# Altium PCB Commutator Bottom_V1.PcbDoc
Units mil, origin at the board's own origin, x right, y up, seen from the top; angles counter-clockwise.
Board outline 2389.49 x 2550.21 mil, 2 copper layers (Top Layer, Bottom Layer), stack 61.756 mil thick; 13 components, 19 nets, 72 pads, 18 vias.
Unrouted connection lines stored in the file: 13.
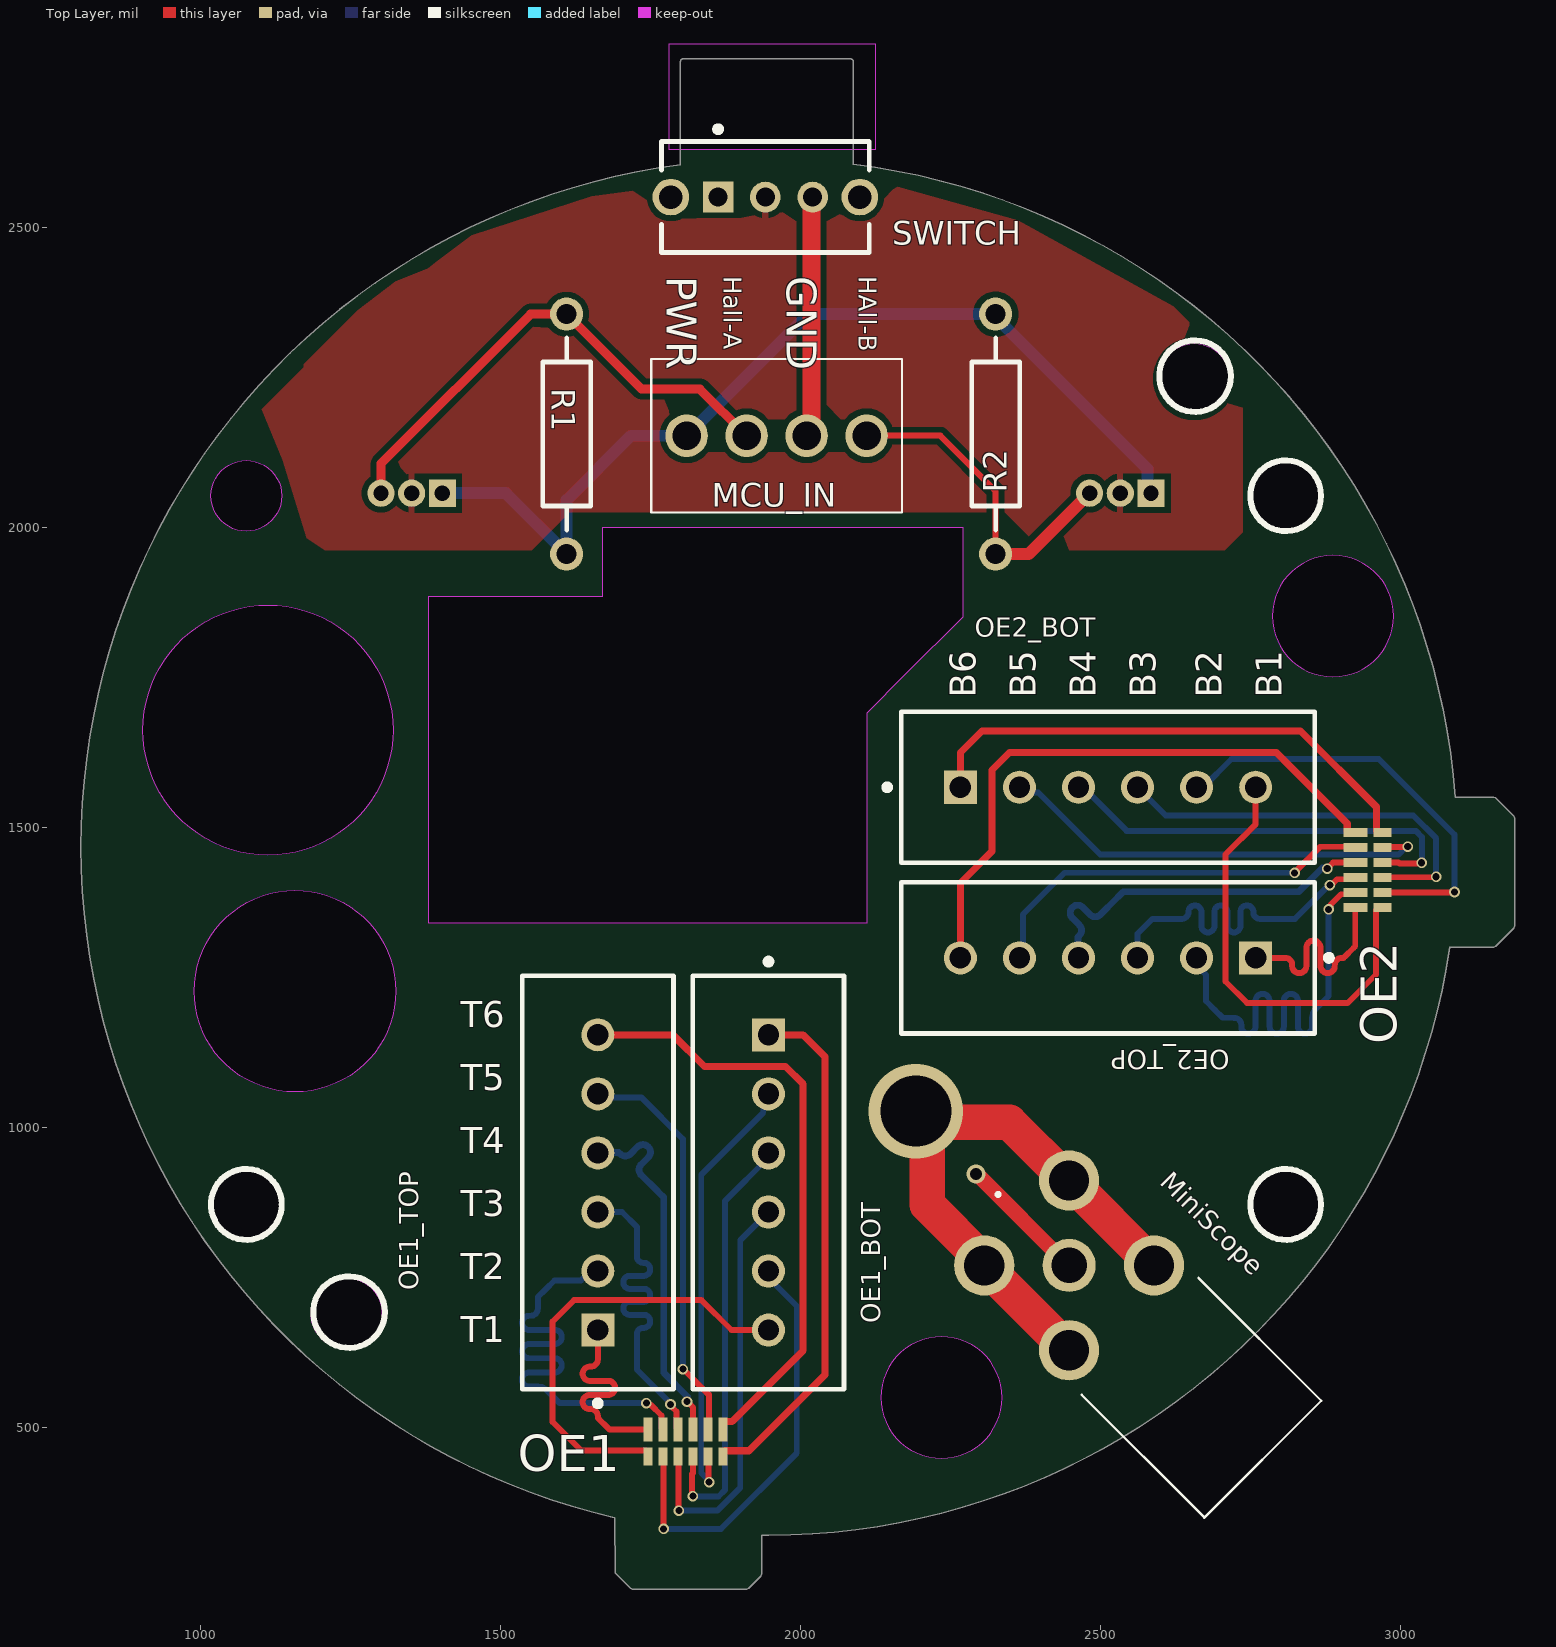
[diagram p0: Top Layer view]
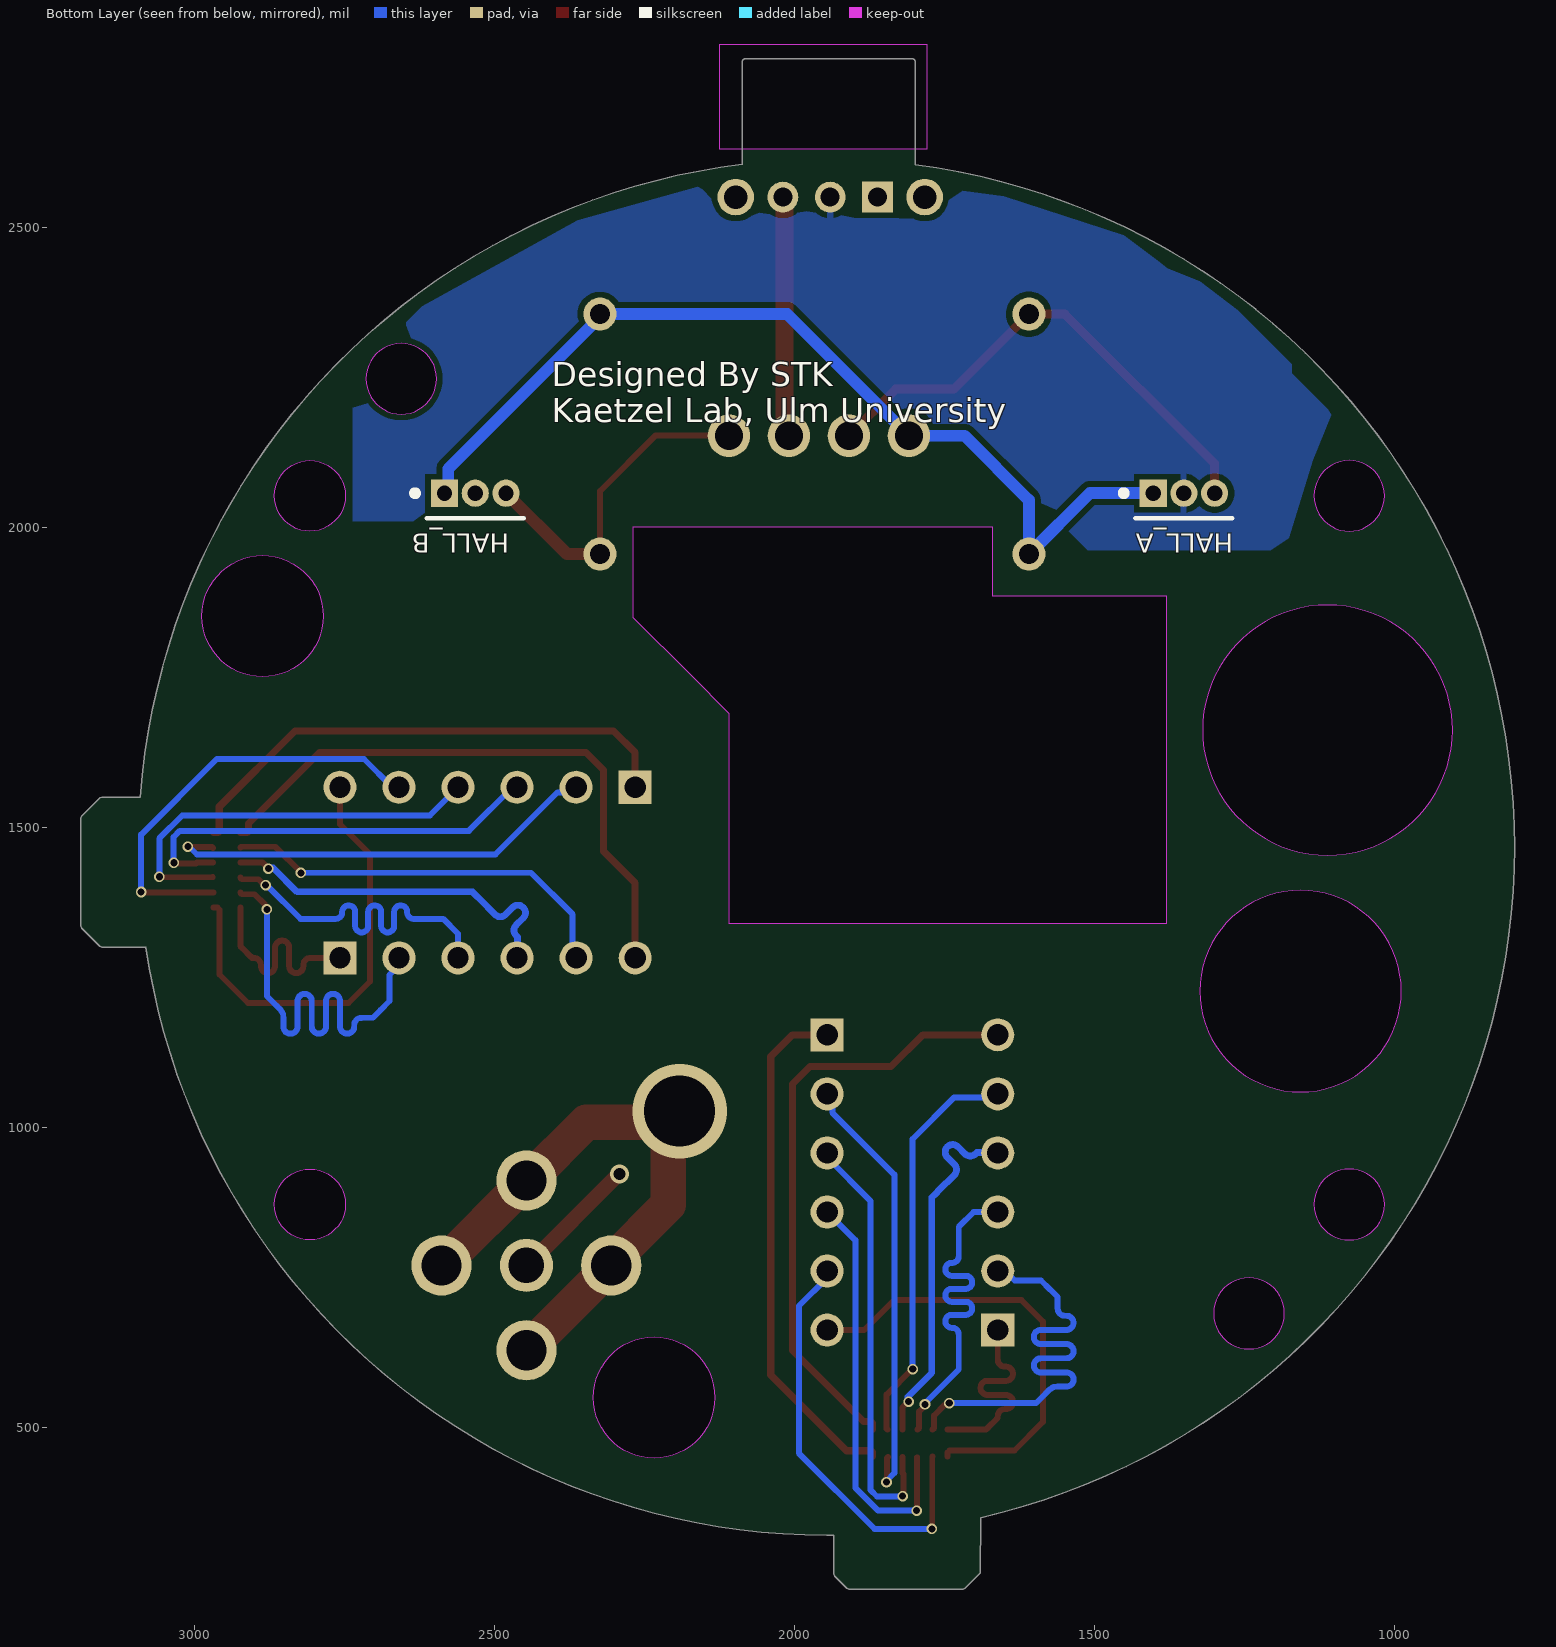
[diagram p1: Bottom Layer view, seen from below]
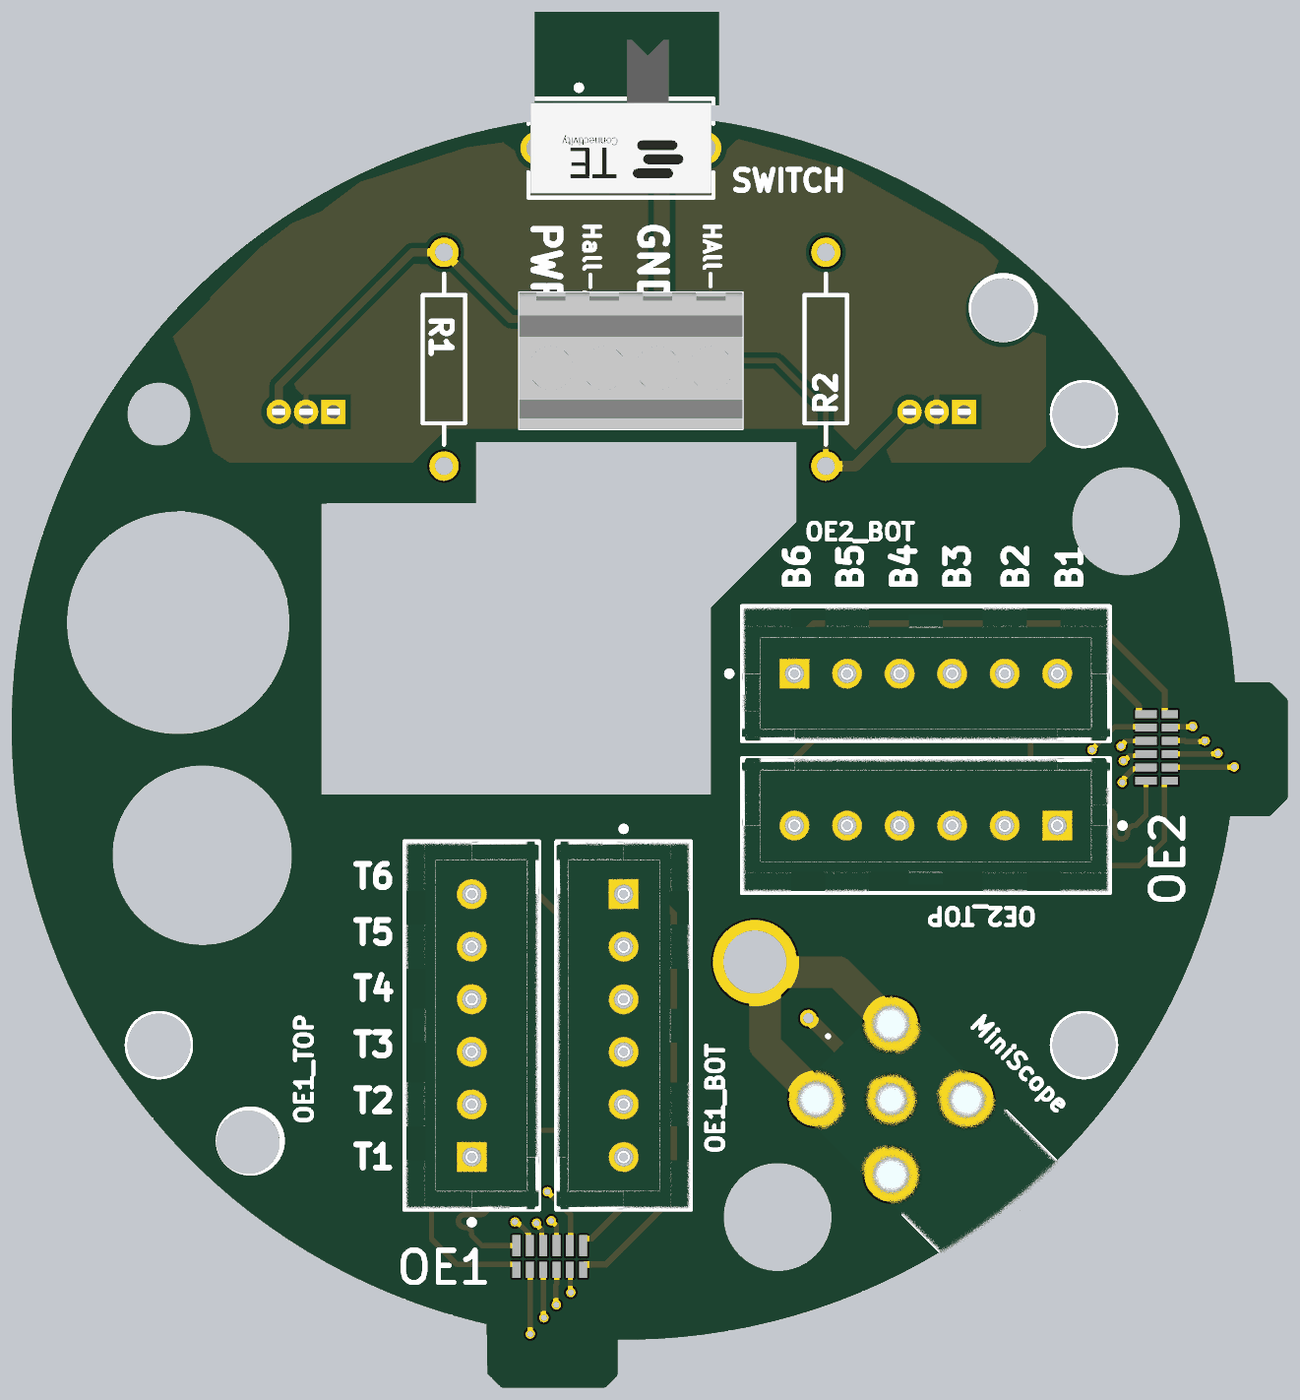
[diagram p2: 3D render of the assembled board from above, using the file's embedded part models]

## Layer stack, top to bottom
Top Solder: solder mask 1, SM-001, Dk 4
Top Layer: signal copper 1.378
Dielectric 1: core 59, Core-043, Dk 4.3
Bottom Layer: signal copper 1.378
Bottom Solder: solder mask 1, SM-001, Dk 4

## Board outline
1691.45,256.45 1716.45,231.45 1720,229.98 1910,229.98 1913.55,231.45 1933.55,251.45 1935.02,255 1935.02,319.88 ccw(c1947.28,1466.56) 1947.28,319.81 ccw(c1947.28,1466.56) 3081.86,1299.98 3155,1299.98 3158.55,1301.45 3188.55,1331.45 3190.02,1335 3190.02,1515 3188.55,1518.55 3158.55,1548.55 3155,1550.01 3090.98,1550.01 ccw(c1947.28,1466.56) 2087.61,2604.69 2087.61,2776.25 ccw(c2083.65,2776.25) 2083.65,2780.2 1803.73,2780.2 ccw(c1803.73,2776.25) 1799.78,2776.25 1799.78,2603.78 ccw(c1947.28,1466.56) 800.53,1466.56 ccw(c1947.28,1466.56) 1689.98,349.05
cut-out: 1112.28,1453.17 cw(c1112.28,1661.56) 903.89,1661.56 cw(c1112.28,1661.56) 1112.28,1869.95 cw(c1112.28,1661.56) 1320.66,1661.56 cw(c1112.28,1661.56)
cut-out: 2786.16,1851.56 ccw(c2887.28,1851.56) 2887.28,1750.44 ccw(c2887.28,1851.56) 2988.39,1851.56 ccw(c2887.28,1851.56) 2887.28,1952.68 ccw(c2887.28,1851.56)
cut-out: 2656.13,2188.06 cw(c2656.13,2247.11) 2597.08,2247.11 cw(c2656.13,2247.11) 2656.13,2306.17 cw(c2656.13,2247.11) 2715.19,2247.11 cw(c2656.13,2247.11)
cut-out: 1243.17,630.31 cw(c1243.17,689.37) 1184.12,689.37 cw(c1243.17,689.37) 1243.17,748.42 cw(c1243.17,689.37) 1302.23,689.37 cw(c1243.17,689.37)
cut-out: 1076.13,1993.06 cw(c1076.13,2052.11) 1017.08,2052.11 cw(c1076.13,2052.11) 1076.13,2111.17 cw(c1076.13,2052.11) 1135.19,2052.11 cw(c1076.13,2052.11)
cut-out: 2749.36,2052.11 ccw(c2808.42,2052.11) 2808.42,1993.06 ccw(c2808.42,2052.11) 2867.47,2052.11 ccw(c2808.42,2052.11) 2808.42,2111.17 ccw(c2808.42,2052.11)
cut-out: 2749.36,871.01 ccw(c2808.42,871.01) 2808.42,811.95 ccw(c2808.42,871.01) 2867.47,871.01 ccw(c2808.42,871.01) 2808.42,930.06 ccw(c2808.42,871.01)
cut-out: 1076.13,811.95 cw(c1076.13,871.01) 1017.08,871.01 cw(c1076.13,871.01) 1076.13,930.06 cw(c1076.13,871.01) 1135.19,871.01 cw(c1076.13,871.01)
cut-out: 2133.61,549.18 ccw(c2234.73,549.18) 2234.73,448.06 ccw(c2234.73,549.18) 2335.85,549.18 ccw(c2234.73,549.18) 2234.73,650.29 ccw(c2234.73,549.18)
cut-out: 1157.28,1058.56 cw(c1157.28,1226.56) 989.27,1226.56 cw(c1157.28,1226.56) 1157.28,1394.56 cw(c1157.28,1226.56) 1325.28,1226.56 cw(c1157.28,1226.56)
cut-out: 1380,1340 1380,1885 1670,1885 1670,2000 2270,2000 2270,1850 2173.75,1753.75 2110,1690 2110,1340
cut-out: 1780,2630 2125,2630 2125,2805 1780,2805

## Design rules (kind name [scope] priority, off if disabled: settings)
Clearance [All] p1: gap=10 ignorepadtopadclearanceinfootprint=FALSE except(0: Arc-Hole Track-Hole SMDPad-Hole THPad-Hole Via-Hole Fill-Hole Poly-Hole Region-Hole Text-Hole)
PolygonConnect [All] p1: connectstyle=Relief reliefconductorwidth=10 reliefentries=4 polygonreliefangle="90 Angle" airgapwidth=10
RoutingVias [All] p1: holewidth=28 width=50 viastyle="Through Hole" minholewidth=28 minwidth=50 maxholewidth=28 maxwidth=50
SolderMaskExpansion [All] p1: expansion=4 istentingtop=FALSE
Width [All] p1: maxlimit=10 minlimit=10 preferedwidth=10
30 further rules are at their usual default settings.

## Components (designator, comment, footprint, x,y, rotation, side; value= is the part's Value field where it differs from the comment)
HALL_A "SS49E" FP-SS49E-MFG 1351.72,2052.11 r180 bottom (schematic designator HAll_A)
HALL_B "SS49E" FP-SS49E-MFG 2532.83,2052.11 r180 bottom
MCU_IN "282834-4" 2828344 1810,2152.19 r0 top
MiniScope "132136RP" 132136RP 2447.49,769.43 r315 top
OE1 "RHD2000-CABLE-DAQ-SIDE" RHD2000_EVAL_BOARD_OMNETICS_PZN-12-AA 1808.1,410.59 r180 top
OE1_BOT "B06B-XASK-1(LF)(SN)" FP-B06B-XASK-1_LF_SN-MFG 1946.33,907.67 r90 top
OE1_TOP "B06B-XASK-1(LF)(SN)" FP-B06B-XASK-1_LF_SN-MFG 1661.96,907.67 r270 top
OE2 "RHD2000-CABLE-DAQ-SIDE" RHD2000_EVAL_BOARD_OMNETICS_PZN-12-AA 3009.41,1428.1 r270 top
OE2_BOT "B06B-XASK-1(LF)(SN)" FP-B06B-XASK-1_LF_SN-MFG 2512.33,1566.33 r180 top
OE2_TOP "B06B-XASK-1(LF)(SN)" FP-B06B-XASK-1_LF_SN-MFG 2512.33,1281.96 r0 top
R1 "" AXIAL-0.4 1610,2155 r270 top value="6 - 10K"
R2 "" AXIAL-0.4 2325,2155 r90 top value="6 - 10K"
SWITCH "1825232-1" FP-1825232-1-MFG 1941.26,2550 r0 top

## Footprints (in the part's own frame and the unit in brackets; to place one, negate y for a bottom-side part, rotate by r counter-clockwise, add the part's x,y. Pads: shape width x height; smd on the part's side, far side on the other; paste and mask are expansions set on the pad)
132136RP [mm]
  round 2.25 hole 1.5: 1(0,0)
  round 2.55 hole 1.7: 2(-2.54,-2.54) 3(2.54,-2.54) 4(2.54,2.54) 5(-2.54,2.54)
  silkscreen extent -4.3,-3.5 11.6,3.5, body extent -3.5,-3.5 11.6,3.5, height 9.96
2828344 [mm]
  round 1.8 hole 1.2: 1(0,0) 2(2.54,0) 3(5.08,0) 4(7.62,0)
  silkscreen extent -1.5,-3.25 9.12,3.25, body extent -1.5,-3.25 9.12,3.25, height 9.93
AXIAL-0.4 [mm] "Axial Device, Thru-Hole; 2 Leads; 0.4 in Pin Spacing"
  round 1.4 hole 0.85: 1(-5.08,0) 2(5.08,0)
  silkscreen extent -4.06,-1.02 4.06,1.02
FP-1825232-1-MFG [mm]
  rect 1.3x1.3 hole 0.8 paste-1000 mask+0: 1(-2,0)
  round 1.3 hole 0.8 paste-1000 mask+0: 2(0,0) 3(2,0)
  round 1.55 hole 1 paste-1000 mask+0: 4(-4,0) 5(4,0)
  silkscreen extent -4.4,-2.35 4.4,3, body extent -4.87,-5.45 4.88,2.45, height 0.25
FP-B06B-XASK-1_LF_SN-MFG [mm]
  rect 1.4x1.4 hole 0.9 paste-1000 mask+0: 1(6.25,0)
  round 1.4 hole 0.9 paste-1000 mask+0: 2(3.75,0) 3(1.25,0) 4(-1.25,0) 5(-3.75,0) 6(-6.25,0)
  silkscreen extent -8.75,-3.2 9.47,3.2, body extent -8.85,-3.3 8.85,3.3, height 0.25
FP-SS49E-MFG [mm]
  rect 1.15x1.15 hole 0.65 paste-1000 mask+0: 1(-1.3,0.11)
  round 1.15 hole 0.65 paste-1000 mask+0: 2(0,0.11) 3(1.3,0.11)
  silkscreen extent -2.68,-0.95 2.05,0.23, body extent -2.05,-0.8 2.05,0.8, height 5.1
RHD2000_EVAL_BOARD_OMNETICS_PZN-12-AA [mil]
  rect 15x30 smd: B1(62.5,-40) B2(37.5,-40) B3(12.5,-40) B4(-12.5,-40) B5(-37.5,-40) B6(-62.5,-40)
  rect 15x40 smd: T1(62.5,-85) T2(37.5,-85) T3(12.5,-85) T4(-12.5,-85) T5(-37.5,-85) T6(-62.5,-85)

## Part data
HALL_A HALL_B: library part CMP-11168-000005-1, "SENSOR LINEAR ANALOG RADIAL", Case/Package=TO-226-3, Input Current=10mA, Leakage Current=10uA, Max Operating Temperature=150°C, Max Supply Voltage=6.5V, Max Supply Voltage (DC)=10V, Min Operating Temperature=-40°C, Min Supply Voltage=2.7V, Min Supply Voltage (DC)=4V, Operating Supply Current=6mA, Output Current=1.5mA, Output Voltage=1.75mV, Package Quantity=1000
MCU_IN: "Connector", Manufacturer_Name="TE Connectivity"
MiniScope: "Connector", Manufacturer_Name=Amphenol
OE1 OE2: "Omnetics PZN-12-AA RHD2000 socket - DAQ side"
OE1_BOT OE1_TOP OE2_BOT OE2_TOP: library part CMP-17439-000268-1, "CONN HEADER VERT 6POS 2.5MM", Color=Beige, Contact Resistance=20mR, Current Rating=3A, Flammability Rating="UL94 V-0", Insulation Color=Natural, Insulation Resistance=1GR, Max Operating Temperature=85°C, Max Voltage Rating (AC)=250V, Min Operating Temperature=-25°C
R1 R2: library part Res2, "Resistor"
SWITCH: library part CMP-03405-000001-1, "SWITCH SLIDE SPDT 200MA 30V", Contact Current Rating=0.2A, Contact Resistance=20mΩ, Manufacturer="TE Connectivity", Operating Force=200gf, Temperature="-20°C to +70°C", Temperature Range High=+70°C, Temperature Range Low=-20°C, Voltage Rating Dc=30V

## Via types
v1: diameter 17.72, hole 11.81, Top Layer to Bottom Layer, 16 vias
v2: diameter 157.48, hole 118.11, Top Layer to Bottom Layer, 1 vias
v3: diameter 31.5, hole 19.68, Top Layer to Bottom Layer, 1 vias

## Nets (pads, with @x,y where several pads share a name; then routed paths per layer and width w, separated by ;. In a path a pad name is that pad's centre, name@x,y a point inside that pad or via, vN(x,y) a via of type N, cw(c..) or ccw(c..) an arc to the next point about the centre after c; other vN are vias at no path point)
+5V: HALL_A.1 HALL_B.1 MCU_IN.1 R1.2 R2.2 | length 1585.4
  Bottom Layer w19.68: R1.2 1610,2045 1717.19,2152.19 MCU_IN.1 2012.81,2355 2320,2355 2577.92,2097.08 2577.92,2062.53 HALL_B.1
  Bottom Layer w20: HALL_A.1 1508.56,2056.44 R1.2
A_B1: OE1.B1 OE1_BOT.6 OE2.B1 OE2_BOT.6 | length 1499.1
  Top Layer w9.84: OE1.B1 1745.6,457.45 1742.1,460.95 1634.11,460.95 1586.73,508.33 1586.73,675.86 1622.6,711.73 1834.55,711.73 1884.67,661.61 OE1_BOT.6 ; OE2_BOT.6 2758.39,1504.67 2708.27,1454.55 2708.27,1242.6 2744.14,1206.73 2911.67,1206.73 2959.05,1254.11 2959.05,1362.1 2962.55,1365.6 OE2.B1
A_B2: OE1.B2 OE1_BOT.5 OE2.B2 OE2_BOT.5 | length 1436.2
  Top Layer w9.84: OE1.B2 1771.14,450.05 1771.14,330.8 v1(1771.69,330.26) ; OE2.B2 2969.95,1391.14 3089.2,1391.14 v1(3089.74,1391.69)
  Bottom Layer w9.84: v1(1771.69,330.26) 1867.4,330.26 1993.57,456.43 1993.57,701.84 1946.33,749.07 OE1_BOT.5 ; OE2_BOT.5 2670.93,1566.33 2718.16,1613.57 2963.57,1613.57 3089.74,1487.4 v1(3089.74,1391.69)
A_B3: OE1.B3 OE1_BOT.4 OE2.B3 OE2_BOT.4 | length 1374.3
  Top Layer w8: OE1.B3 OE1.B3@1796.48,449.72 ; OE2.B3 OE2.B3@2970.28,1416.48
  Top Layer w9.84: OE1.B3@1796.48,449.72 1796.38,449.62 1796.38,361.46 v1(1797.15,360.68) ; OE2.B3@2970.28,1416.48 2970.38,1416.37 3058.54,1416.38 v1(3059.32,1417.15)
  Bottom Layer w9.84: v1(1797.15,360.68) 1861.13,360.68 1899.31,398.86 1899.31,811.43 OE1_BOT.4@1945.96,858.08 ; OE2_BOT.4@2561.92,1565.96 2608.57,1519.31 3021.14,1519.31 3059.32,1481.13 v1(3059.32,1417.15)
A_B4: OE1.B4 OE1_BOT.3 OE2.B4 OE2_BOT.3 | length 1432.9
  Top Layer w8: OE1.B4 OE1.B4@1820.96,450.24 ; OE2.B4 OE2.B4@2969.76,1440.96
  Top Layer w9.84: v1(1820.45,384.85) 1819.11,386.19 1819.11,421.67 1820.96,423.52 OE1.B4@1820.96,450.24 ; OE2.B4@2969.76,1440.96 2996.48,1440.96 2998.33,1439.11 3033.81,1439.11 v1(3035.15,1440.45)
  Bottom Layer w9.84: v1@1820.99,384.31 1863.24,384.31 1873.74,394.81 1873.74,876.53 1946.33,949.13 OE1_BOT.3 ; OE2_BOT.3 2470.87,1566.34 2543.47,1493.74 3025.19,1493.74 3035.69,1483.24 v1@3035.69,1440.99
A_B5: OE1.B5 OE1_BOT.2 OE2.B5 OE2_BOT.2 | length 1485.4
  Top Layer w8: OE1.B5@1845.1,450.09 OE1.B5 ; OE2.B5 OE2.B5@2969.91,1465.1
  Top Layer w9.84: OE1.B5@1845.1,450.09 1846.53,448.66 1846.53,409.01 v1(1847.46,408.09) ; OE2.B5@2969.91,1465.1 2971.34,1466.53 3010.99,1466.53 v1(3011.91,1467.46)
  Bottom Layer w9.84: v1(1847.46,408.09) 1847.46,410.22 1834.38,423.29 1834.38,920.68 1937.7,1024 1937.7,1046.68 OE1_BOT.2 ; OE2_BOT.2 2373.32,1557.7 2396,1557.7 2499.32,1454.38 2996.71,1454.38 3009.78,1467.46 v1(3011.91,1467.46)
A_B6: OE1.B6 OE1_BOT.1 OE2.B6 OE2_BOT.1 | length 1740.2
  Top Layer w11.81: OE1.B6 1870.6,457.98 1873.1,460.48 1913.86,460.48 2040.29,586.91 2040.29,1117.61 2004.17,1153.73 OE1_BOT.1 ; OE2_BOT.1 2266.27,1624.17 2302.39,1660.29 2833.09,1660.29 2959.52,1533.86 2959.52,1493.1 2962.02,1490.6 OE2.B6
A_T1: OE1.T1 OE1_TOP.1 OE2.T1 OE2_TOP.1 | length 713
  Top Layer w9.84: OE1_TOP.1 1661.96,650.64 1661.96,612.5 cw(c1650.15,612.5) 1650.15,600.69 1648.46,600.69 ccw(c1648.46,588.88) 1648.46,577.07 1678.94,577.07 cw(c1678.94,565.26) 1678.94,553.45 1648.46,553.45 ccw(c1648.46,541.63) 1648.46,529.82 1650.15,529.82 cw(c1650.15,518.01) 1661.96,518.01 1661.96,515.11 1663.98,513.09 1678.47,498.6 1681.48,495.59 OE1.T1 ; OE2_TOP.1 2769.36,1281.96 2807.5,1281.96 cw(c2807.5,1270.15) 2819.31,1270.15 2819.31,1268.46 ccw(c2831.12,1268.46) 2842.93,1268.46 2842.93,1298.94 cw(c2854.74,1298.94) 2866.55,1298.94 2866.55,1268.46 ccw(c2878.37,1268.46) 2890.18,1268.46 2890.18,1270.15 cw(c2901.99,1270.15) 2901.99,1281.96 2904.89,1281.96 2906.91,1283.98 2921.4,1298.47 2924.41,1301.48 OE2.T1
A_T2: OE1.T2 OE1_TOP.2 OE2.T2 OE2_TOP.2 | length 1557.2
  Top Layer w9.84: v1(1742.81,539.9) 1744.41,539.9 1747.36,536.95 1750.33,536.95 1768.02,519.26 1768.02,498.17 OE1.T2 ; v1(2880.1,1362.81) 2880.1,1364.41 2883.05,1367.36 2883.05,1370.33 2900.74,1388.02 2921.83,1388.02 OE2.T2
  Bottom Layer w9.84: 1575,729.54 1562.11,716.66 1562.11,711.74 1562.09,697.31 cw(c1550.28,697.33) 1550.28,685.52 1547.55,685.52 ccw(c1547.55,673.71) 1547.55,661.9 1590.11,661.9 cw(c1590.11,650.09) 1590.11,638.28 1547.48,638.28 ccw(c1547.48,626.47) 1547.48,614.65 1590.04,614.65 cw(c1590.04,602.84) 1590.04,591.03 1547.41,591.03 ccw(c1547.41,579.22) 1547.41,567.41 1562.52,567.41 cw(c1562.52,547.25) 1576.78,561.5 1581.71,556.58 1598.38,539.9 v1(1742.81,539.9) ; 1575.19,729.52 1589.94,744.27 1633.71,744.27 1649.48,760.03 OE1_TOP.2 ; OE2_TOP.2 2659.97,1269.48 2675.73,1253.71 2675.73,1209.94 2690.48,1195.19 ; 2690.46,1195 2703.34,1182.11 2708.26,1182.11 2722.69,1182.09 cw(c2722.67,1170.28) 2734.48,1170.28 2734.48,1167.55 ccw(c2746.29,1167.55) 2758.1,1167.55 2758.1,1210.11 cw(c2769.91,1210.11) 2781.72,1210.11 2781.72,1167.48 ccw(c2793.53,1167.48) 2805.35,1167.48 2805.35,1210.04 cw(c2817.16,1210.04) 2828.97,1210.04 2828.97,1167.41 ccw(c2840.78,1167.41) 2852.59,1167.41 2852.59,1182.52 cw(c2872.75,1182.52) 2858.45,1196.73 2858.5,1196.78 2863.42,1201.71 2880.1,1218.38 v1(2880.1,1362.81)
A_T3: OE1.T3 OE1_TOP.3 OE2.T3 OE2_TOP.3 | length 1221.3
  Top Layer w9.84: v1(1783.23,537.88) 1783.23,535.75 1793.02,525.96 1793.02,498.17 OE1.T3 ; v1(2882.12,1403.23) 2884.25,1403.23 2894.04,1413.02 2921.83,1413.02 OE2.T3
  Bottom Layer w9.84: OE1_TOP.3 1702.17,858.46 1726.99,833.63 1726.99,789.4 1726.99,784.48 ccw(c1737.82,784.48) 1737.82,773.65 1738.57,773.65 cw(c1738.57,762.83) 1749.4,762.83 cw(c1738.57,762.83) 1738.57,752 1715.27,752 ccw(c1715.27,741.17) 1704.44,741.17 ccw(c1715.27,741.17) 1715.27,730.35 1738.57,730.35 cw(c1738.57,719.52) 1749.4,719.52 cw(c1738.57,719.52) 1738.57,708.69 1715.27,708.69 ccw(c1715.27,697.87) 1704.44,697.87 ccw(c1715.27,697.87) 1715.27,687.04 1738.57,687.04 cw(c1738.57,676.21) 1749.4,676.21 cw(c1738.57,676.21) 1738.57,665.39 1737.82,665.39 ccw(c1737.82,654.56) 1726.99,654.56 1726.99,627.62 1726.99,596.04 1783.23,539.8 v1(1783.23,537.88) ; OE2_TOP.3 2561.54,1322.17 2586.37,1346.99 2630.6,1346.99 2635.52,1346.99 ccw(c2635.52,1357.82) 2646.35,1357.82 2646.35,1358.57 cw(c2657.17,1358.57) 2657.17,1369.4 cw(c2657.17,1358.57) 2668,1358.57 2668,1335.27 ccw(c2678.83,1335.27) 2678.83,1324.44 ccw(c2678.83,1335.27) 2689.65,1335.27 2689.65,1358.57 cw(c2700.48,1358.57) 2700.48,1369.4 cw(c2700.48,1358.57) 2711.31,1358.57 2711.31,1335.27 ccw(c2722.13,1335.27) 2722.13,1324.44 ccw(c2722.13,1335.27) 2732.96,1335.27 2732.96,1358.57 cw(c2743.79,1358.57) 2743.79,1369.4 cw(c2743.79,1358.57) 2754.61,1358.57 2754.61,1357.82 ccw(c2765.44,1357.82) 2765.44,1346.99 2792.38,1346.99 2823.96,1346.99 2880.2,1403.23 v1(2882.12,1403.23)
A_T4: OE1.T4 OE1_TOP.4 OE2.T4 OE2_TOP.4 | length 1228.3
  Top Layer w9.84: v1(1810.6,542.24) 1811.12,542.24 1820.6,532.75 OE1.T4 ; v1(2877.76,1430.6) 2877.76,1431.12 2887.25,1440.6 OE2.T4
  Bottom Layer w11.22: OE1_TOP.4 1666.15,961.07 1669.66,957.57 1693.2,957.57 1696.83,957.57 1698.98,955.42 ccw(c1707.82,964.25) 1716.66,955.42 1728.35,967.11 cw(c1737.19,958.27) 1746.03,967.11 cw(c1737.19,958.27) 1746.03,949.43 1734.34,937.74 ccw(c1743.18,928.9) 1734.34,920.06 1760.43,893.97 1764.4,890 1772,882.4 1772,590.28 1811.73,550.55 1811.73,543.37 v1(1810.6,542.24) ; OE2_TOP.4 2458.93,1286.15 2462.43,1289.66 2462.43,1313.2 2462.43,1316.83 2464.58,1318.98 ccw(c2455.75,1327.82) 2464.58,1336.66 2452.89,1348.35 cw(c2461.73,1357.19) 2452.89,1366.03 cw(c2461.73,1357.19) 2470.57,1366.03 2482.26,1354.34 ccw(c2491.1,1363.18) 2499.94,1354.34 2526.03,1380.43 2530,1384.4 2537.6,1392 2829.72,1392 2869.45,1431.73 2876.63,1431.73 v1(2877.76,1430.6)
A_T5: OE1.T5 OE1_TOP.5 OE2.T5 OE2_TOP.5 | length 1351.3
  Top Layer w9.84: v1@1804.45,596.63 1847.12,553.96 1847.12,497.11 OE1.T5 ; v1@2823.37,1424.45 2866.04,1467.12 2922.89,1467.12 OE2.T5
  Bottom Layer w9.84: OE1_TOP.5 1667.86,1049.41 1734.48,1049.41 1803.8,980.09 v1@1803.8,596.77 ; OE2_TOP.5 2370.59,1287.86 2370.59,1354.48 2439.91,1423.8 v1@2823.23,1423.8
  other v1: 1803.66,596.63 2823.37,1423.66
A_T6: OE1.T6 OE1_TOP.6 OE2.T6 OE2_TOP.6 | length 2030.6
  Top Layer w11.81: OE1_TOP.6 1786.76,1153.73 1839.64,1100.86 1975.08,1100.86 2004.31,1071.63 2004.31,627.34 1885.94,508.97 1873.1,508.97 1870.6,506.47 OE1.T6 ; OE2_TOP.6 2266.27,1406.76 2319.14,1459.64 2319.14,1595.08 2348.37,1624.31 2792.66,1624.31 2911.03,1505.94 2911.03,1493.1 2913.53,1490.6 OE2.T6
D1: HALL_A.3 MCU_IN.2 R1.1 | length 845.9
  Top Layer w15: HALL_A.3 1300.54,2105.54 1550,2355 R1.1 1735,2230 1832.19,2230 MCU_IN.2
D2: HALL_B.3 MCU_IN.4 R2.1 | length 557
  Top Layer w10: MCU_IN.4 2232.81,2152.19 2325,2060 R2.1 ; HALL_B.3@2481.53,2056.56 HALL_B.3
  Top Layer w20: R2.1 2379.97,1955 HALL_B.3@2481.53,2056.56
GND: MCU_IN.3 SWITCH.3 | length 405.4
  Top Layer w30: MCU_IN.3@2017.82,2145.54 2017.82,2547.82 SWITCH.3
GND_miniscope: MiniScope.2 MiniScope.3 MiniScope.4 MiniScope.5 | length 1007.4
  Top Layer w59.06: MiniScope.3 2304.08,771.41 2304.08,777.77 2211.11,870.74 v2@2211.11,1007.73 ; MiniScope.4 2445.5,912.84 2442.99,912.84 2348.1,1007.73 v2@2211.11,1007.73 ; v2@2211.11,1007.73 v2(2192.28,1026.56) v2@2211.11,1007.73
GND_OUT: HALL_A.2 HALL_B.2 SWITCH.2
SIG: MiniScope.1 | length 218.2
  Top Layer w10: v3(2292.28,921.56) v3@2293.81,921.56 ; MiniScope.1@2445.95,769.43 MiniScope.1
  Top Layer w25: v3@2293.81,921.56 MiniScope.1@2445.95,769.43
pads on no net: SWITCH.1 SWITCH.4 SWITCH.5

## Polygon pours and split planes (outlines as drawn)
GND_OUT on Top Layer "NONET_L04_P-001" (solid, remove dead copper, pour order 0): 1102.28,2196.56 1172.28,2266.56 1172.28,2271.56 1252.28,2351.56 1262.28,2361.56 1325.61,2409.89 1379.78,2431.56 1392.28,2441.56 1452.28,2486.56 1652.28,2551.56 1945.61,2591.56 2127.28,2576.56 2362.28,2511.56 2621.03,2367.81 2737.28,2251.56 2737.28,1991.56 2707.28,1961.56 2403.44,1961.56 2340,2025 1615,2025 1551.56,1961.56 1207.28,1961.56 1177.28,1981.56 1137.28,2111.56
GND_OUT on Bottom Layer "NONET_L04_P-001" (solid, remove dead copper, pour order 1): 1112.28,2196.56 1172.28,2256.56 1172.28,2271.56 1252.28,2351.56 1262.28,2361.56 1325.61,2409.89 1379.78,2431.56 1392.28,2441.56 1452.28,2486.56 1652.28,2551.56 1945.61,2591.56 2127.28,2576.56 2362.28,2511.56 2621.03,2367.81 2737.28,2251.56 2737.28,2010 1560.72,2010 1512.28,1961.56 1207.28,1961.56 1177.28,1981.56 1137.28,2111.56 1102.28,2196.56

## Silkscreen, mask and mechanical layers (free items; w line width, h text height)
Top Overlay:
  circle w10: c2657.28,2251.56 r59.69
  circle w10: c1247.28,691.56 r59.69
  circle w10: c1076.13,871.01 r59.06
  circle w10: c2808.42,2052.11 r59.06
  circle w10: c2808.42,871.01 r59.06
  text "PWR" at 1777,2418 h50 r270
  text "Hall-A" at 1872,2418 h30 r270
  text "GND" at 1977,2418 h50 r270
  text "HAll-B" at 2097,2418 h30 r270
  text "B6" at 2291.8,1715.85 h43.31 r90
  text "B5" at 2391.89,1715.85 h43.31 r90
  text "B4" at 2491.97,1715.85 h43.31 r90
  text "B3" at 2592.06,1715.85 h43.31 r90
  text "B2" at 2701.56,1715.85 h43.31 r90
  text "B1" at 2802.23,1715.85 h43.31 r90
  text "T6" at 1433.67,1166.35 h43.31
  text "T5" at 1433.67,1061.35 h43.31
  text "T4" at 1433.67,956.35 h43.31
  text "T3" at 1433.67,851.35 h43.31
  text "T2" at 1433.67,746.35 h43.31
  text "T1" at 1433.67,641.35 h43.31
Bottom Overlay:
  text "Designed By STK / Kaetzel Lab, Ulm University" at 2405,2175 h40
Mechanical 1:
  circle w10: c2235,550 r101.12
  circle w10: c1157.28,1226.56 r168
  circle w10: c1112.28,1661.56 r208.39
  circle w10: c2887.28,1851.56 r101.12
Top Courtyard:
  circle w10: c1076.13,2052.11 r59.06
Mechanical 13:
  circle w10: c1947.28,1466.56 r1141.73
  lines w10: 1695,355 1695,260 1720,235 1910,235 1930,255 1930,320 ; 3075,1305 3155,1305 3185,1335 3185,1466.75 3185,1515 3155,1545 3085,1545 ; 1380,1340 1380,1885 1670,1885 1670,2000 2270,2000 2270,1850 2173.75,1753.75 2110,1690 2110,1340 1380,1340
Mechanical 26:
  circle w10: c1542.28,1991.56 r275.59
